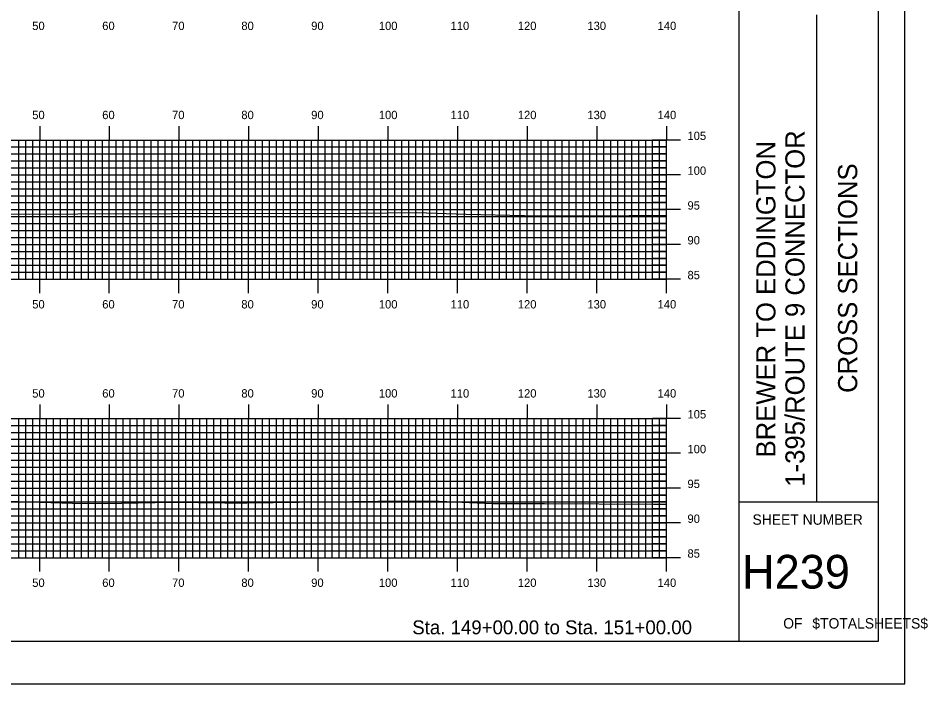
# Model space of a CAD drawing. Extents: x 1778319 to 1778662, y 442591 to 442811.
# Drawn here: x 1778531.2 to 1778661.8, y 442590.5 to 442686.2 of the extents above; entities that cross this region are included whole.
import ezdxf

# ---------------------------------------------------------------- set-up
doc = ezdxf.new("R2010")
doc.units = 0
for name, color, linetype in [('BORDER', 7, 'Continuous'), ('H_V ANNOTATION', 7, 'Continuous'), ('MAJOR', 7, 'Continuous'), ('MINOR', 7, 'Continuous'), ('PLOT BOUNDARY', 7, 'Continuous'), ('S_Roadway_Centerline', 7, 'Continuous')]:
    doc.layers.add(name, color=color, linetype=linetype)

msp = doc.modelspace()

# ---------------------------------------------------------------- linework, layer by layer
at = {"layer": 'BORDER'}
for p, q in [((1778634.7, 442596.67), (1778634.7, 442806.67)), ((1778645.89, 442616.67), (1778645.89, 442686.67)), ((1778634.7, 442616.67), (1778654.7, 442616.67))]:
    msp.add_line(p, q, dxfattribs=at)
msp.add_lwpolyline([(1778334.7, 442596.67), (1778654.7, 442596.67), (1778654.7, 442806.67), (1778334.7, 442806.67)], close=True, dxfattribs=at)
at = {"layer": 'MAJOR'}
for p, q in [((1778534.3, 442670.67), (1778534.3, 442668.67)), ((1778544.3, 442670.67), (1778544.3, 442668.67)), ((1778554.3, 442670.67), (1778554.3, 442668.67)), ((1778564.3, 442670.67), (1778564.3, 442668.67)), ((1778574.3, 442670.67), (1778574.3, 442668.67)), ((1778584.3, 442670.67), (1778584.3, 442668.67)), ((1778594.3, 442670.67), (1778594.3, 442668.67)), ((1778604.3, 442670.67), (1778604.3, 442668.67)), ((1778614.3, 442670.67), (1778614.3, 442668.67)), ((1778624.3, 442670.67), (1778624.3, 442668.67)), ((1778344.3, 442668.67), (1778624.3, 442668.67)), ((1778344.3, 442668.67), (1778624.3, 442668.67)), ((1778534.3, 442648.67), (1778534.3, 442668.67)), ((1778544.3, 442648.67), (1778544.3, 442668.67)), ((1778554.3, 442648.67), (1778554.3, 442668.67)), ((1778564.3, 442648.67), (1778564.3, 442668.67)), ((1778574.3, 442648.67), (1778574.3, 442668.67)), ((1778584.3, 442648.67), (1778584.3, 442668.67)), ((1778594.3, 442648.67), (1778594.3, 442668.67)), ((1778604.3, 442648.67), (1778604.3, 442668.67)), ((1778614.3, 442648.67), (1778614.3, 442668.67)), ((1778626.31, 442668.67), (1778622.3, 442668.67)), ((1778624.3, 442648.67), (1778624.3, 442668.67)), ((1778624.3, 442648.67), (1778624.3, 442668.67)), ((1778344.3, 442663.67), (1778624.3, 442663.67)), ((1778626.31, 442663.67), (1778622.3, 442663.67)), ((1778344.3, 442658.67), (1778624.3, 442658.67)), ((1778626.31, 442658.67), (1778622.3, 442658.67)), ((1778344.3, 442653.67), (1778624.3, 442653.67)), ((1778626.31, 442653.67), (1778622.3, 442653.67)), ((1778344.3, 442648.67), (1778624.3, 442648.67)), ((1778344.3, 442648.67), (1778624.3, 442648.67)), ((1778534.3, 442646.66), (1778534.3, 442648.67)), ((1778544.3, 442646.66), (1778544.3, 442648.67)), ((1778554.3, 442646.66), (1778554.3, 442648.67)), ((1778564.3, 442646.66), (1778564.3, 442648.67)), ((1778574.3, 442646.66), (1778574.3, 442648.67)), ((1778584.3, 442646.66), (1778584.3, 442648.67)), ((1778594.3, 442646.66), (1778594.3, 442648.67)), ((1778604.3, 442646.66), (1778604.3, 442648.67)), ((1778614.3, 442646.66), (1778614.3, 442648.67)), ((1778626.31, 442648.67), (1778622.3, 442648.67)), ((1778624.3, 442646.66), (1778624.3, 442648.67)), ((1778534.3, 442630.67), (1778534.3, 442628.67)), ((1778544.3, 442630.67), (1778544.3, 442628.67)), ((1778554.3, 442630.67), (1778554.3, 442628.67)), ((1778564.3, 442630.67), (1778564.3, 442628.67)), ((1778574.3, 442630.67), (1778574.3, 442628.67)), ((1778584.3, 442630.67), (1778584.3, 442628.67)), ((1778594.3, 442630.67), (1778594.3, 442628.67)), ((1778604.3, 442630.67), (1778604.3, 442628.67)), ((1778614.3, 442630.67), (1778614.3, 442628.67)), ((1778624.3, 442630.67), (1778624.3, 442628.67)), ((1778344.3, 442628.67), (1778624.3, 442628.67)), ((1778344.3, 442628.67), (1778624.3, 442628.67)), ((1778534.3, 442608.67), (1778534.3, 442628.67)), ((1778544.3, 442608.67), (1778544.3, 442628.67)), ((1778554.3, 442608.67), (1778554.3, 442628.67)), ((1778564.3, 442608.67), (1778564.3, 442628.67)), ((1778574.3, 442608.67), (1778574.3, 442628.67)), ((1778584.3, 442608.67), (1778584.3, 442628.67)), ((1778594.3, 442608.67), (1778594.3, 442628.67)), ((1778604.3, 442608.67), (1778604.3, 442628.67)), ((1778614.3, 442608.67), (1778614.3, 442628.67)), ((1778626.31, 442628.67), (1778622.3, 442628.67)), ((1778624.3, 442608.67), (1778624.3, 442628.67)), ((1778624.3, 442608.67), (1778624.3, 442628.67)), ((1778344.3, 442623.67), (1778624.3, 442623.67)), ((1778626.31, 442623.67), (1778622.3, 442623.67)), ((1778344.3, 442618.67), (1778624.3, 442618.67)), ((1778626.31, 442618.67), (1778622.3, 442618.67)), ((1778344.3, 442613.67), (1778624.3, 442613.67)), ((1778626.31, 442613.67), (1778622.3, 442613.67)), ((1778344.3, 442608.67), (1778624.3, 442608.67)), ((1778344.3, 442608.67), (1778624.3, 442608.67)), ((1778534.3, 442606.66), (1778534.3, 442608.67)), ((1778544.3, 442606.66), (1778544.3, 442608.67)), ((1778554.3, 442606.66), (1778554.3, 442608.67)), ((1778564.3, 442606.66), (1778564.3, 442608.67)), ((1778574.3, 442606.66), (1778574.3, 442608.67)), ((1778584.3, 442606.66), (1778584.3, 442608.67)), ((1778594.3, 442606.66), (1778594.3, 442608.67)), ((1778604.3, 442606.66), (1778604.3, 442608.67)), ((1778614.3, 442606.66), (1778614.3, 442608.67)), ((1778626.31, 442608.67), (1778622.3, 442608.67)), ((1778624.3, 442606.66), (1778624.3, 442608.67))]:
    msp.add_line(p, q, dxfattribs=at)
at = {"layer": 'MINOR'}
for p, q in [((1778531.3, 442648.67), (1778531.3, 442668.67)), ((1778532.3, 442648.67), (1778532.3, 442668.67)), ((1778533.3, 442648.67), (1778533.3, 442668.67)), ((1778535.3, 442648.67), (1778535.3, 442668.67)), ((1778536.3, 442648.67), (1778536.3, 442668.67)), ((1778537.3, 442648.67), (1778537.3, 442668.67)), ((1778538.3, 442648.67), (1778538.3, 442668.67)), ((1778539.3, 442648.67), (1778539.3, 442668.67)), ((1778540.3, 442648.67), (1778540.3, 442668.67)), ((1778541.3, 442648.67), (1778541.3, 442668.67)), ((1778542.3, 442648.67), (1778542.3, 442668.67)), ((1778543.3, 442648.67), (1778543.3, 442668.67)), ((1778545.3, 442648.67), (1778545.3, 442668.67)), ((1778546.3, 442648.67), (1778546.3, 442668.67)), ((1778547.3, 442648.67), (1778547.3, 442668.67)), ((1778548.3, 442648.67), (1778548.3, 442668.67)), ((1778549.3, 442648.67), (1778549.3, 442668.67)), ((1778550.3, 442648.67), (1778550.3, 442668.67)), ((1778551.3, 442648.67), (1778551.3, 442668.67)), ((1778552.3, 442648.67), (1778552.3, 442668.67)), ((1778553.3, 442648.67), (1778553.3, 442668.67)), ((1778555.3, 442648.67), (1778555.3, 442668.67)), ((1778556.3, 442648.67), (1778556.3, 442668.67)), ((1778557.3, 442648.67), (1778557.3, 442668.67)), ((1778558.3, 442648.67), (1778558.3, 442668.67)), ((1778559.3, 442648.67), (1778559.3, 442668.67)), ((1778560.3, 442648.67), (1778560.3, 442668.67)), ((1778561.3, 442648.67), (1778561.3, 442668.67)), ((1778562.3, 442648.67), (1778562.3, 442668.67)), ((1778563.3, 442648.67), (1778563.3, 442668.67)), ((1778565.3, 442648.67), (1778565.3, 442668.67)), ((1778566.3, 442648.67), (1778566.3, 442668.67)), ((1778567.3, 442648.67), (1778567.3, 442668.67)), ((1778568.3, 442648.67), (1778568.3, 442668.67)), ((1778569.3, 442648.67), (1778569.3, 442668.67)), ((1778570.3, 442648.67), (1778570.3, 442668.67)), ((1778571.3, 442648.67), (1778571.3, 442668.67)), ((1778572.3, 442648.67), (1778572.3, 442668.67)), ((1778573.3, 442648.67), (1778573.3, 442668.67)), ((1778575.3, 442648.67), (1778575.3, 442668.67)), ((1778576.3, 442648.67), (1778576.3, 442668.67)), ((1778577.3, 442648.67), (1778577.3, 442668.67)), ((1778578.3, 442648.67), (1778578.3, 442668.67)), ((1778579.3, 442648.67), (1778579.3, 442668.67)), ((1778580.3, 442648.67), (1778580.3, 442668.67)), ((1778581.3, 442648.67), (1778581.3, 442668.67)), ((1778582.3, 442648.67), (1778582.3, 442668.67)), ((1778583.3, 442648.67), (1778583.3, 442668.67)), ((1778585.3, 442648.67), (1778585.3, 442668.67)), ((1778586.3, 442648.67), (1778586.3, 442668.67)), ((1778587.3, 442648.67), (1778587.3, 442668.67)), ((1778588.3, 442648.67), (1778588.3, 442668.67)), ((1778589.3, 442648.67), (1778589.3, 442668.67)), ((1778590.3, 442648.67), (1778590.3, 442668.67)), ((1778591.3, 442648.67), (1778591.3, 442668.67)), ((1778592.3, 442648.67), (1778592.3, 442668.67)), ((1778593.3, 442648.67), (1778593.3, 442668.67)), ((1778595.3, 442648.67), (1778595.3, 442668.67)), ((1778596.3, 442648.67), (1778596.3, 442668.67)), ((1778597.3, 442648.67), (1778597.3, 442668.67)), ((1778598.3, 442648.67), (1778598.3, 442668.67)), ((1778599.3, 442648.67), (1778599.3, 442668.67)), ((1778600.3, 442648.67), (1778600.3, 442668.67)), ((1778601.3, 442648.67), (1778601.3, 442668.67)), ((1778602.3, 442648.67), (1778602.3, 442668.67)), ((1778603.3, 442648.67), (1778603.3, 442668.67)), ((1778605.3, 442648.67), (1778605.3, 442668.67)), ((1778606.3, 442648.67), (1778606.3, 442668.67)), ((1778607.3, 442648.67), (1778607.3, 442668.67)), ((1778608.3, 442648.67), (1778608.3, 442668.67)), ((1778609.3, 442648.67), (1778609.3, 442668.67)), ((1778610.3, 442648.67), (1778610.3, 442668.67)), ((1778611.3, 442648.67), (1778611.3, 442668.67)), ((1778612.3, 442648.67), (1778612.3, 442668.67)), ((1778613.3, 442648.67), (1778613.3, 442668.67)), ((1778615.3, 442648.67), (1778615.3, 442668.67)), ((1778616.3, 442648.67), (1778616.3, 442668.67)), ((1778617.3, 442648.67), (1778617.3, 442668.67)), ((1778618.3, 442648.67), (1778618.3, 442668.67)), ((1778619.3, 442648.67), (1778619.3, 442668.67)), ((1778620.3, 442648.67), (1778620.3, 442668.67)), ((1778621.3, 442648.67), (1778621.3, 442668.67)), ((1778622.3, 442648.67), (1778622.3, 442668.67)), ((1778623.3, 442648.67), (1778623.3, 442668.67)), ((1778344.3, 442667.67), (1778624.3, 442667.67)), ((1778624.3, 442667.67), (1778622.3, 442667.67)), ((1778344.3, 442666.67), (1778624.3, 442666.67)), ((1778624.3, 442666.67), (1778622.3, 442666.67)), ((1778344.3, 442665.67), (1778624.3, 442665.67)), ((1778344.3, 442664.67), (1778624.3, 442664.67)), ((1778624.3, 442665.67), (1778622.3, 442665.67)), ((1778624.3, 442664.67), (1778622.3, 442664.67)), ((1778344.3, 442662.67), (1778624.3, 442662.67)), ((1778624.3, 442662.67), (1778622.3, 442662.67)), ((1778344.3, 442661.67), (1778624.3, 442661.67)), ((1778344.3, 442660.67), (1778624.3, 442660.67)), ((1778624.3, 442661.67), (1778622.3, 442661.67)), ((1778624.3, 442660.67), (1778622.3, 442660.67)), ((1778344.3, 442659.67), (1778624.3, 442659.67)), ((1778624.3, 442659.67), (1778622.3, 442659.67)), ((1778344.3, 442657.67), (1778624.3, 442657.67)), ((1778344.3, 442656.67), (1778624.3, 442656.67)), ((1778624.3, 442657.67), (1778622.3, 442657.67)), ((1778624.3, 442656.67), (1778622.3, 442656.67)), ((1778344.3, 442655.67), (1778624.3, 442655.67)), ((1778624.3, 442655.67), (1778622.3, 442655.67)), ((1778344.3, 442654.67), (1778624.3, 442654.67)), ((1778624.3, 442654.67), (1778622.3, 442654.67)), ((1778344.3, 442652.67), (1778624.3, 442652.67)), ((1778624.3, 442652.67), (1778622.3, 442652.67)), ((1778344.3, 442651.67), (1778624.3, 442651.67)), ((1778624.3, 442651.67), (1778622.3, 442651.67)), ((1778344.3, 442650.67), (1778624.3, 442650.67)), ((1778624.3, 442650.67), (1778622.3, 442650.67)), ((1778344.3, 442649.67), (1778624.3, 442649.67)), ((1778624.3, 442649.67), (1778622.3, 442649.67)), ((1778531.3, 442608.67), (1778531.3, 442628.67)), ((1778532.3, 442608.67), (1778532.3, 442628.67)), ((1778533.3, 442608.67), (1778533.3, 442628.67)), ((1778535.3, 442608.67), (1778535.3, 442628.67)), ((1778536.3, 442608.67), (1778536.3, 442628.67)), ((1778537.3, 442608.67), (1778537.3, 442628.67)), ((1778538.3, 442608.67), (1778538.3, 442628.67)), ((1778539.3, 442608.67), (1778539.3, 442628.67)), ((1778540.3, 442608.67), (1778540.3, 442628.67)), ((1778541.3, 442608.67), (1778541.3, 442628.67)), ((1778542.3, 442608.67), (1778542.3, 442628.67)), ((1778543.3, 442608.67), (1778543.3, 442628.67)), ((1778545.3, 442608.67), (1778545.3, 442628.67)), ((1778546.3, 442608.67), (1778546.3, 442628.67)), ((1778547.3, 442608.67), (1778547.3, 442628.67)), ((1778548.3, 442608.67), (1778548.3, 442628.67)), ((1778549.3, 442608.67), (1778549.3, 442628.67)), ((1778550.3, 442608.67), (1778550.3, 442628.67)), ((1778551.3, 442608.67), (1778551.3, 442628.67)), ((1778552.3, 442608.67), (1778552.3, 442628.67)), ((1778553.3, 442608.67), (1778553.3, 442628.67)), ((1778555.3, 442608.67), (1778555.3, 442628.67)), ((1778556.3, 442608.67), (1778556.3, 442628.67)), ((1778557.3, 442608.67), (1778557.3, 442628.67)), ((1778558.3, 442608.67), (1778558.3, 442628.67)), ((1778559.3, 442608.67), (1778559.3, 442628.67)), ((1778560.3, 442608.67), (1778560.3, 442628.67)), ((1778561.3, 442608.67), (1778561.3, 442628.67)), ((1778562.3, 442608.67), (1778562.3, 442628.67)), ((1778563.3, 442608.67), (1778563.3, 442628.67)), ((1778565.3, 442608.67), (1778565.3, 442628.67)), ((1778566.3, 442608.67), (1778566.3, 442628.67)), ((1778567.3, 442608.67), (1778567.3, 442628.67)), ((1778568.3, 442608.67), (1778568.3, 442628.67)), ((1778569.3, 442608.67), (1778569.3, 442628.67)), ((1778570.3, 442608.67), (1778570.3, 442628.67)), ((1778571.3, 442608.67), (1778571.3, 442628.67)), ((1778572.3, 442608.67), (1778572.3, 442628.67)), ((1778573.3, 442608.67), (1778573.3, 442628.67)), ((1778575.3, 442608.67), (1778575.3, 442628.67)), ((1778576.3, 442608.67), (1778576.3, 442628.67)), ((1778577.3, 442608.67), (1778577.3, 442628.67)), ((1778578.3, 442608.67), (1778578.3, 442628.67)), ((1778579.3, 442608.67), (1778579.3, 442628.67)), ((1778580.3, 442608.67), (1778580.3, 442628.67)), ((1778581.3, 442608.67), (1778581.3, 442628.67)), ((1778582.3, 442608.67), (1778582.3, 442628.67)), ((1778583.3, 442608.67), (1778583.3, 442628.67)), ((1778585.3, 442608.67), (1778585.3, 442628.67)), ((1778586.3, 442608.67), (1778586.3, 442628.67)), ((1778587.3, 442608.67), (1778587.3, 442628.67)), ((1778588.3, 442608.67), (1778588.3, 442628.67)), ((1778589.3, 442608.67), (1778589.3, 442628.67)), ((1778590.3, 442608.67), (1778590.3, 442628.67)), ((1778591.3, 442608.67), (1778591.3, 442628.67)), ((1778592.3, 442608.67), (1778592.3, 442628.67)), ((1778593.3, 442608.67), (1778593.3, 442628.67)), ((1778595.3, 442608.67), (1778595.3, 442628.67)), ((1778596.3, 442608.67), (1778596.3, 442628.67)), ((1778597.3, 442608.67), (1778597.3, 442628.67)), ((1778598.3, 442608.67), (1778598.3, 442628.67)), ((1778599.3, 442608.67), (1778599.3, 442628.67)), ((1778600.3, 442608.67), (1778600.3, 442628.67)), ((1778601.3, 442608.67), (1778601.3, 442628.67)), ((1778602.3, 442608.67), (1778602.3, 442628.67)), ((1778603.3, 442608.67), (1778603.3, 442628.67)), ((1778605.3, 442608.67), (1778605.3, 442628.67)), ((1778606.3, 442608.67), (1778606.3, 442628.67)), ((1778607.3, 442608.67), (1778607.3, 442628.67)), ((1778608.3, 442608.67), (1778608.3, 442628.67)), ((1778609.3, 442608.67), (1778609.3, 442628.67)), ((1778610.3, 442608.67), (1778610.3, 442628.67)), ((1778611.3, 442608.67), (1778611.3, 442628.67)), ((1778612.3, 442608.67), (1778612.3, 442628.67)), ((1778613.3, 442608.67), (1778613.3, 442628.67)), ((1778615.3, 442608.67), (1778615.3, 442628.67)), ((1778616.3, 442608.67), (1778616.3, 442628.67)), ((1778617.3, 442608.67), (1778617.3, 442628.67)), ((1778618.3, 442608.67), (1778618.3, 442628.67)), ((1778619.3, 442608.67), (1778619.3, 442628.67)), ((1778620.3, 442608.67), (1778620.3, 442628.67)), ((1778621.3, 442608.67), (1778621.3, 442628.67)), ((1778622.3, 442608.67), (1778622.3, 442628.67)), ((1778623.3, 442608.67), (1778623.3, 442628.67)), ((1778344.3, 442627.67), (1778624.3, 442627.67)), ((1778344.3, 442626.67), (1778624.3, 442626.67)), ((1778624.3, 442627.67), (1778622.3, 442627.67)), ((1778624.3, 442626.67), (1778622.3, 442626.67)), ((1778344.3, 442625.67), (1778624.3, 442625.67)), ((1778624.3, 442625.67), (1778622.3, 442625.67)), ((1778344.3, 442624.67), (1778624.3, 442624.67)), ((1778624.3, 442624.67), (1778622.3, 442624.67)), ((1778344.3, 442622.67), (1778624.3, 442622.67)), ((1778624.3, 442622.67), (1778622.3, 442622.67)), ((1778344.3, 442621.67), (1778624.3, 442621.67)), ((1778624.3, 442621.67), (1778622.3, 442621.67)), ((1778344.3, 442620.67), (1778624.3, 442620.67)), ((1778624.3, 442620.67), (1778622.3, 442620.67)), ((1778344.3, 442619.67), (1778624.3, 442619.67)), ((1778624.3, 442619.67), (1778622.3, 442619.67)), ((1778344.3, 442617.67), (1778624.3, 442617.67)), ((1778624.3, 442617.67), (1778622.3, 442617.67)), ((1778344.3, 442616.67), (1778624.3, 442616.67)), ((1778624.3, 442616.67), (1778622.3, 442616.67)), ((1778344.3, 442615.67), (1778624.3, 442615.67)), ((1778624.3, 442615.67), (1778622.3, 442615.67)), ((1778344.3, 442614.67), (1778624.3, 442614.67)), ((1778624.3, 442614.67), (1778622.3, 442614.67)), ((1778344.3, 442612.67), (1778624.3, 442612.67)), ((1778624.3, 442612.67), (1778622.3, 442612.67)), ((1778344.3, 442611.67), (1778624.3, 442611.67)), ((1778624.3, 442611.67), (1778622.3, 442611.67)), ((1778344.3, 442610.67), (1778624.3, 442610.67)), ((1778344.3, 442609.67), (1778624.3, 442609.67)), ((1778624.3, 442610.67), (1778622.3, 442610.67)), ((1778624.3, 442609.67), (1778622.3, 442609.67))]:
    msp.add_line(p, q, dxfattribs=at)
at = {"layer": 'PLOT BOUNDARY'}
msp.add_lwpolyline([(1778318.52, 442590.55), (1778658.52, 442590.55), (1778658.52, 442810.55), (1778318.52, 442810.55)], close=True, dxfattribs=at)
at = {"layer": 'S_Roadway_Centerline'}
for points in [[(1778524.41, 442658.02), (1778539.78, 442658.08), (1778553.26, 442658.12), (1778557.49, 442658.14), (1778571.66, 442658.1), (1778580.33, 442658.17), (1778588.41, 442658.25), (1778595.55, 442658.04), (1778603.89, 442657.83), (1778610.67, 442657.76), (1778618.91, 442657.84), (1778622.83, 442657.83), (1778624.3, 442657.84)], [(1778526.59, 442616.87), (1778539.02, 442616.52), (1778543.61, 442616.46), (1778553.31, 442616.62), (1778560.86, 442616.57), (1778564.04, 442616.56), (1778582.83, 442616.81), (1778587.37, 442616.8), (1778591.65, 442616.78), (1778599.28, 442616.47), (1778606.75, 442616.47), (1778622.44, 442616.35), (1778624.3, 442616.35)]]:
    msp.add_lwpolyline(points, dxfattribs=at)

# ---------------------------------------------------------------- texts
at = {"layer": 'BORDER'}
for s, p in [('1-395/ROUTE 9 CONNECTOR', (1778644.11, 442618.87)), ('BREWER TO EDDINGTON', (1778639.93, 442623.07)), ('CROSS SECTIONS', (1778651.67, 442632.34))]:
    msp.add_text(s, height=2.7557, rotation=90, dxfattribs=at).set_placement(p)
for s, height, p in [('SHEET NUMBER', 1.4905, (1778636.63, 442613.4)), ('H239', 4.839, (1778635.14, 442604.23)), ('OF', 1.491, (1778641.04, 442598.49)), ('$TOTALSHEETS$', 1.4905, (1778645.22, 442598.49))]:
    msp.add_text(s, height=height, dxfattribs=at).set_placement(p)
at = {"layer": 'H_V ANNOTATION'}
for s, height, p in [('50', 1.2, (1778533.23, 442684.47)), ('60', 1.2, (1778543.28, 442684.47)), ('70', 1.2, (1778553.31, 442684.47)), ('80', 1.2, (1778563.25, 442684.47)), ('90', 1.2, (1778573.28, 442684.47)), ('100', 1.2, (1778582.99, 442684.47)), ('110', 1.2, (1778593.29, 442684.47)), ('120', 1.2, (1778602.94, 442684.47)), ('130', 1.2, (1778612.93, 442684.47)), ('140', 1.2, (1778623.01, 442684.47)), ('50', 1.2, (1778533.23, 442671.67)), ('60', 1.2, (1778543.28, 442671.67)), ('70', 1.2, (1778553.31, 442671.67)), ('80', 1.2, (1778563.25, 442671.67)), ('90', 1.2, (1778573.28, 442671.67)), ('100', 1.2, (1778582.99, 442671.67)), ('110', 1.2, (1778593.29, 442671.67)), ('120', 1.2, (1778602.94, 442671.67)), ('130', 1.2, (1778612.93, 442671.67)), ('140', 1.2, (1778623.01, 442671.67)), ('105', 1.2, (1778627.3, 442668.67)), ('100', 1.2, (1778627.3, 442663.67)), ('95', 1.2, (1778627.3, 442658.67)), ('90', 1.2, (1778627.3, 442653.67)), ('85', 1.2, (1778627.3, 442648.67)), ('50', 1.2, (1778533.23, 442644.47)), ('60', 1.2, (1778543.28, 442644.47)), ('70', 1.2, (1778553.31, 442644.47)), ('80', 1.2, (1778563.25, 442644.47)), ('90', 1.2, (1778573.28, 442644.47)), ('100', 1.2, (1778582.99, 442644.47)), ('110', 1.2, (1778593.29, 442644.47)), ('120', 1.2, (1778602.94, 442644.47)), ('130', 1.2, (1778612.93, 442644.47)), ('140', 1.2, (1778623.01, 442644.47)), ('50', 1.2, (1778533.23, 442631.67)), ('60', 1.2, (1778543.28, 442631.67)), ('70', 1.2, (1778553.31, 442631.67)), ('80', 1.2, (1778563.25, 442631.67)), ('90', 1.2, (1778573.28, 442631.67)), ('100', 1.2, (1778582.99, 442631.67)), ('110', 1.2, (1778593.29, 442631.67)), ('120', 1.2, (1778602.94, 442631.67)), ('130', 1.2, (1778612.93, 442631.67)), ('140', 1.2, (1778623.01, 442631.67)), ('105', 1.2, (1778627.3, 442628.67)), ('100', 1.2, (1778627.3, 442623.67)), ('95', 1.2, (1778627.3, 442618.67)), ('90', 1.2, (1778627.3, 442613.67)), ('85', 1.2, (1778627.3, 442608.67)), ('50', 1.2, (1778533.23, 442604.47)), ('60', 1.2, (1778543.28, 442604.47)), ('70', 1.2, (1778553.31, 442604.47)), ('80', 1.2, (1778563.25, 442604.47)), ('90', 1.2, (1778573.28, 442604.47)), ('100', 1.2, (1778582.99, 442604.47)), ('110', 1.2, (1778593.29, 442604.47)), ('120', 1.2, (1778602.94, 442604.47)), ('130', 1.2, (1778612.93, 442604.47)), ('140', 1.2, (1778623.01, 442604.47)), ('Sta. 149+00.00 to Sta. 151+00.00', 2.0004, (1778587.79, 442597.66))]:
    msp.add_text(s, height=height, dxfattribs=at).set_placement(p)

doc.saveas('drawing.dxf')
